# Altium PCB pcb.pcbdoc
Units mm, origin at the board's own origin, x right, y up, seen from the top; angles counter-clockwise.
Board outline 152.4 x 101.6 mm, 2 copper layers (Top Layer, Bottom Layer); 31 components, 27 nets, 116 pads, 42 vias.
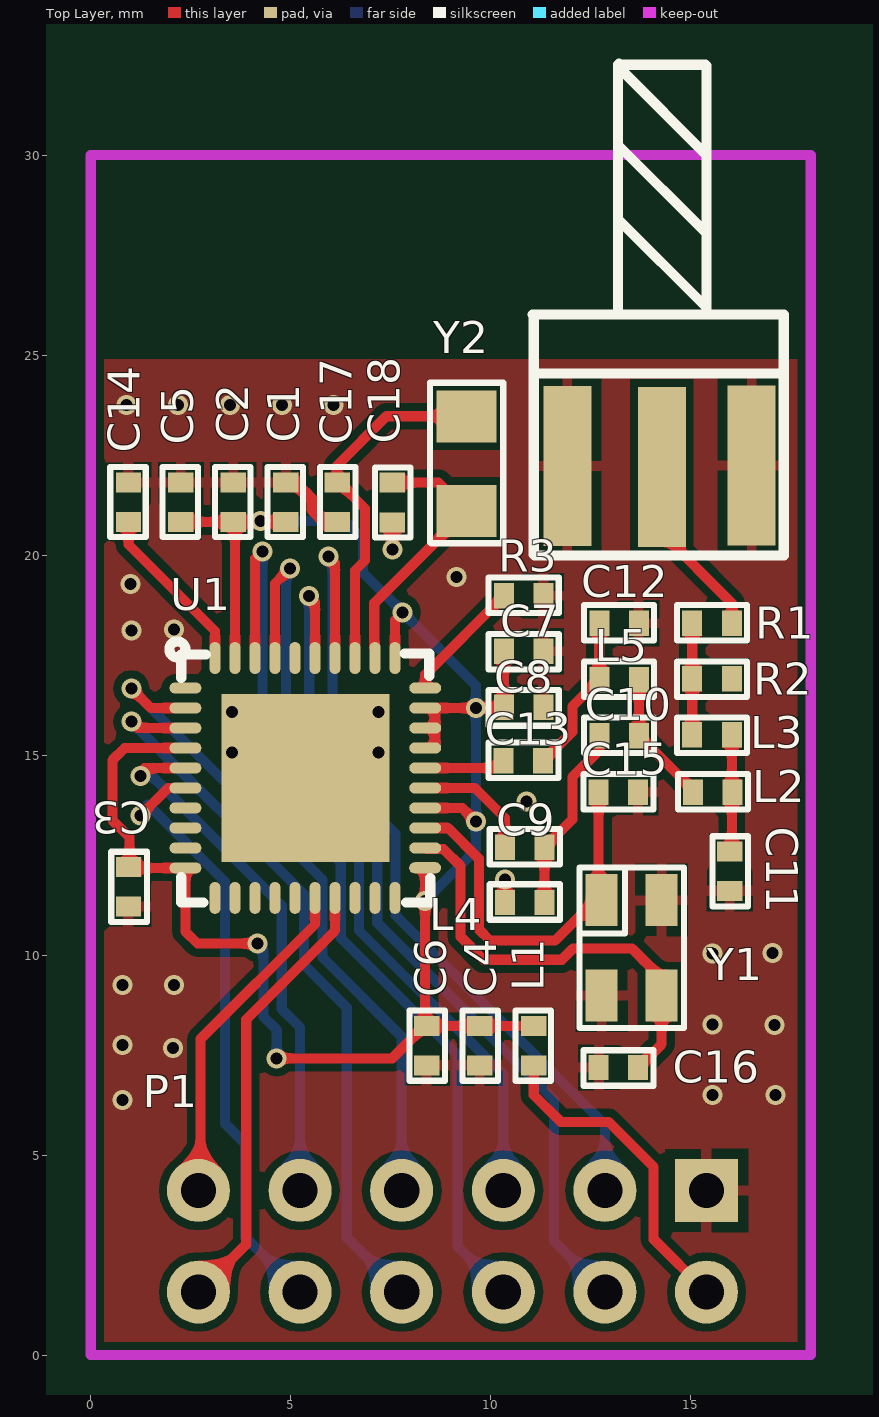
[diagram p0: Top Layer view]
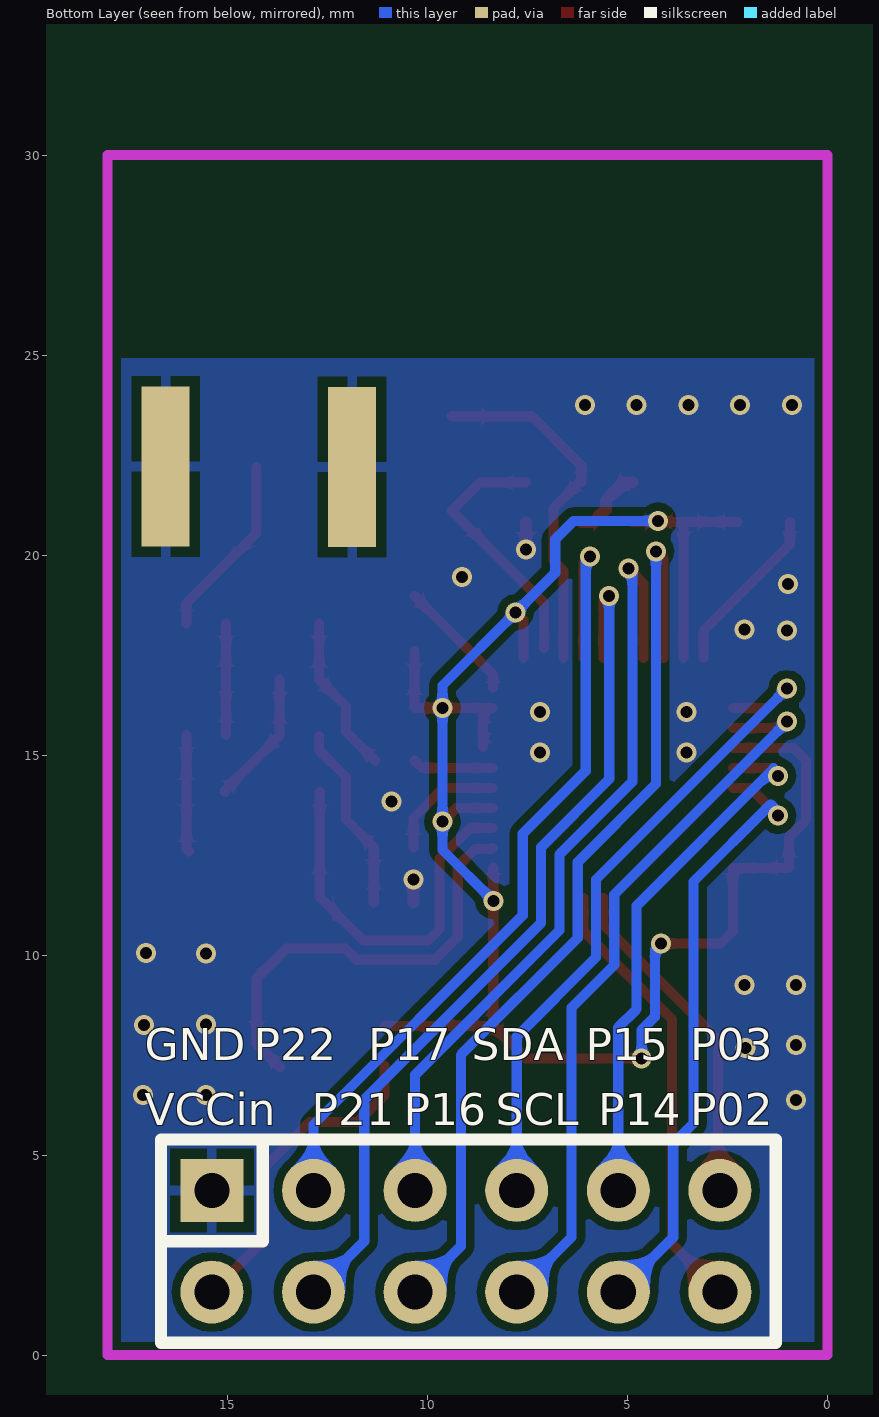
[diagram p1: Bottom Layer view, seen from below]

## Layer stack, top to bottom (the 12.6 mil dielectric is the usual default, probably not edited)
Top Solder: solder mask 0.0102, Solder Resist, Dk 3.5
Top Layer: signal copper 0.0356
Dielectric1: dielectric 0.32, FR-4, Dk 4.8
Bottom Layer: signal copper 0.0356
Bottom Solder: solder mask 0.0102, Solder Resist, Dk 3.5

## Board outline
-67.589,-36.627 84.811,-36.627 84.811,64.973 -67.589,64.973

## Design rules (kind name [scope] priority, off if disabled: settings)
Clearance [All] p1: gap=0.203 ignorepadtopadclearanceinfootprint=FALSE
MinimumSolderMaskSliver [All] p1 off: minsoldermaskwidth=0.254
PolygonConnect PolygonConnect_86 [All vs IsNamedPolygon('Top Layer-GND')] p1: thpad.connectstyle=Relief thpad.reliefconductorwidth=0.254 thpad.reliefentries=4 thpad.polygonreliefangle="90 Angle" thpad.airgapwidth=0.254 smdpad.connectstyle=Relief smdpad.reliefconductorwidth=0.254 smdpad.reliefentries=4 smdpad.polygonreliefangle="90 Angle" smdpad.airgapwidth=0.254 via.connectstyle=Direct via.reliefconductorwidth=0.254 via.reliefentries=4 via.polygonreliefangle="90 Angle" via.airgapwidth=0.254
PolygonConnect PolygonConnect_85 [All vs IsNamedPolygon('GND_L01_P020')] p2: thpad.connectstyle=Relief thpad.reliefconductorwidth=0.254 thpad.reliefentries=4 thpad.polygonreliefangle="90 Angle" thpad.airgapwidth=0.254 smdpad.connectstyle=Relief smdpad.reliefconductorwidth=0.254 smdpad.reliefentries=4 smdpad.polygonreliefangle="90 Angle" smdpad.airgapwidth=0.254 via.connectstyle=Direct via.reliefconductorwidth=0.254 via.reliefentries=4 via.polygonreliefangle="90 Angle" via.airgapwidth=0.254
PolygonConnect PolygonConnect_84 [All vs IsNamedPolygon('Bottom Layer-GND')] p3: thpad.connectstyle=Relief thpad.reliefconductorwidth=0.254 thpad.reliefentries=4 thpad.polygonreliefangle="90 Angle" thpad.airgapwidth=0.254 smdpad.connectstyle=Relief smdpad.reliefconductorwidth=0.254 smdpad.reliefentries=4 smdpad.polygonreliefangle="90 Angle" smdpad.airgapwidth=0.254 via.connectstyle=Direct via.reliefconductorwidth=0.254 via.reliefentries=4 via.polygonreliefangle="90 Angle" via.airgapwidth=0.254
PolygonConnect PolygonConnect_83 [All vs IsNamedPolygon('AGND-top')] p4: thpad.connectstyle=Relief thpad.reliefconductorwidth=0.508 thpad.reliefentries=4 thpad.polygonreliefangle="90 Angle" thpad.airgapwidth=0.254 smdpad.connectstyle=Relief smdpad.reliefconductorwidth=0.508 smdpad.reliefentries=4 smdpad.polygonreliefangle="90 Angle" smdpad.airgapwidth=0.254 via.connectstyle=Direct via.reliefconductorwidth=0.254 via.reliefentries=4 via.polygonreliefangle="90 Angle" via.airgapwidth=0.254
PolygonConnect PolygonConnect_82 [All vs IsNamedPolygon('Totalcurrent-bottom')] p5: thpad.connectstyle=Relief thpad.reliefconductorwidth=0.508 thpad.reliefentries=4 thpad.polygonreliefangle="90 Angle" thpad.airgapwidth=0.254 smdpad.connectstyle=Relief smdpad.reliefconductorwidth=0.508 smdpad.reliefentries=4 smdpad.polygonreliefangle="90 Angle" smdpad.airgapwidth=0.254 via.connectstyle=Direct via.reliefconductorwidth=0.254 via.reliefentries=4 via.polygonreliefangle="90 Angle" via.airgapwidth=0.254
PolygonConnect PolygonConnect_81 [All vs IsNamedPolygon('GND-top')] p6: thpad.connectstyle=Relief thpad.reliefconductorwidth=0.508 thpad.reliefentries=4 thpad.polygonreliefangle="90 Angle" thpad.airgapwidth=0.254 smdpad.connectstyle=Relief smdpad.reliefconductorwidth=0.508 smdpad.reliefentries=4 smdpad.polygonreliefangle="90 Angle" smdpad.airgapwidth=0.254 via.connectstyle=Direct via.reliefconductorwidth=0.254 via.reliefentries=4 via.polygonreliefangle="90 Angle" via.airgapwidth=0.254
PolygonConnect PolygonConnect_80 [All vs IsNamedPolygon('GND-bottom')] p7: thpad.connectstyle=Relief thpad.reliefconductorwidth=0.508 thpad.reliefentries=4 thpad.polygonreliefangle="90 Angle" thpad.airgapwidth=0.254 smdpad.connectstyle=Relief smdpad.reliefconductorwidth=0.508 smdpad.reliefentries=4 smdpad.polygonreliefangle="90 Angle" smdpad.airgapwidth=0.254 via.connectstyle=Direct via.reliefconductorwidth=0.254 via.reliefentries=4 via.polygonreliefangle="90 Angle" via.airgapwidth=0.254
PolygonConnect PolygonConnect_79 [All vs IsNamedPolygon('AGND-bottom')] p8: thpad.connectstyle=Relief thpad.reliefconductorwidth=0.508 thpad.reliefentries=4 thpad.polygonreliefangle="90 Angle" thpad.airgapwidth=0.254 smdpad.connectstyle=Relief smdpad.reliefconductorwidth=0.508 smdpad.reliefentries=4 smdpad.polygonreliefangle="90 Angle" smdpad.airgapwidth=0.254 via.connectstyle=Direct via.reliefconductorwidth=0.254 via.reliefentries=4 via.polygonreliefangle="90 Angle" via.airgapwidth=0.254
PolygonConnect PolygonConnect_78 [All vs IsNamedPolygon('AGND-BOTTOM')] p9: thpad.connectstyle=Relief thpad.reliefconductorwidth=0.508 thpad.reliefentries=4 thpad.polygonreliefangle="90 Angle" thpad.airgapwidth=0.254 smdpad.connectstyle=Relief smdpad.reliefconductorwidth=0.508 smdpad.reliefentries=4 smdpad.polygonreliefangle="90 Angle" smdpad.airgapwidth=0.254 via.connectstyle=Direct via.reliefconductorwidth=0.254 via.reliefentries=4 via.polygonreliefangle="90 Angle" via.airgapwidth=0.254
PolygonConnect PolygonConnect_77 [All vs IsNamedPolygon('AGND-BOTTOM')] p10: thpad.connectstyle=Relief thpad.reliefconductorwidth=0.508 thpad.reliefentries=4 thpad.polygonreliefangle="90 Angle" thpad.airgapwidth=0.254 smdpad.connectstyle=Relief smdpad.reliefconductorwidth=0.508 smdpad.reliefentries=4 smdpad.polygonreliefangle="90 Angle" smdpad.airgapwidth=0.254 via.connectstyle=Direct via.reliefconductorwidth=0.254 via.reliefentries=4 via.polygonreliefangle="90 Angle" via.airgapwidth=0.254
PolygonConnect PolygonConnect_76 [All vs IsNamedPolygon('Totalcurrent-top')] p11: thpad.connectstyle=Relief thpad.reliefconductorwidth=0.508 thpad.reliefentries=4 thpad.polygonreliefangle="90 Angle" thpad.airgapwidth=0.254 smdpad.connectstyle=Relief smdpad.reliefconductorwidth=0.508 smdpad.reliefentries=4 smdpad.polygonreliefangle="90 Angle" smdpad.airgapwidth=0.254 via.connectstyle=Direct via.reliefconductorwidth=0.254 via.reliefentries=4 via.polygonreliefangle="90 Angle" via.airgapwidth=0.254
PolygonConnect PolygonConnect_75 [All vs IsNamedPolygon('Totalcurrent-bottom')] p12: thpad.connectstyle=Relief thpad.reliefconductorwidth=0.508 thpad.reliefentries=4 thpad.polygonreliefangle="90 Angle" thpad.airgapwidth=0.254 smdpad.connectstyle=Relief smdpad.reliefconductorwidth=0.508 smdpad.reliefentries=4 smdpad.polygonreliefangle="90 Angle" smdpad.airgapwidth=0.254 via.connectstyle=Direct via.reliefconductorwidth=0.254 via.reliefentries=4 via.polygonreliefangle="90 Angle" via.airgapwidth=0.254
PolygonConnect PolygonConnect_74 [All vs IsNamedPolygon('Totalcurrent-bottom')] p13: thpad.connectstyle=Relief thpad.reliefconductorwidth=0.508 thpad.reliefentries=4 thpad.polygonreliefangle="90 Angle" thpad.airgapwidth=0.254 smdpad.connectstyle=Relief smdpad.reliefconductorwidth=0.508 smdpad.reliefentries=4 smdpad.polygonreliefangle="90 Angle" smdpad.airgapwidth=0.254 via.connectstyle=Direct via.reliefconductorwidth=0.254 via.reliefentries=4 via.polygonreliefangle="90 Angle" via.airgapwidth=0.254
PolygonConnect PolygonConnect_73 [All vs IsNamedPolygon('Totalcurrent-top')] p14: connectstyle=Relief reliefconductorwidth=0.254 reliefentries=4 polygonreliefangle="90 Angle" airgapwidth=0.254
PolygonConnect PolygonConnect_72 [All vs IsNamedPolygon('Totalcurrent-top')] p15: thpad.connectstyle=Relief thpad.reliefconductorwidth=0.508 thpad.reliefentries=4 thpad.polygonreliefangle="90 Angle" thpad.airgapwidth=0.254 smdpad.connectstyle=Relief smdpad.reliefconductorwidth=0.508 smdpad.reliefentries=4 smdpad.polygonreliefangle="90 Angle" smdpad.airgapwidth=0.254 via.connectstyle=Direct via.reliefconductorwidth=0.254 via.reliefentries=4 via.polygonreliefangle="90 Angle" via.airgapwidth=0.254
PolygonConnect PolygonConnect_71 [All vs IsNamedPolygon('Totalcurrent-top')] p16: connectstyle=Relief reliefconductorwidth=0.254 reliefentries=4 polygonreliefangle="45 Angle" airgapwidth=0.254
PolygonConnect PolygonConnect_70 [All vs IsNamedPolygon('GND-top')] p17: connectstyle=Relief reliefconductorwidth=0.254 reliefentries=4 polygonreliefangle="45 Angle" airgapwidth=0.254
PolygonConnect PolygonConnect_69 [All vs IsNamedPolygon('GND-bottom')] p18: connectstyle=Relief reliefconductorwidth=0.254 reliefentries=4 polygonreliefangle="45 Angle" airgapwidth=0.254
PolygonConnect PolygonConnect_68 [All vs IsNamedPolygon('GND-top')] p19: connectstyle=Relief reliefconductorwidth=0.254 reliefentries=4 polygonreliefangle="45 Angle" airgapwidth=0.254
PolygonConnect PolygonConnect_67 [All vs IsNamedPolygon('GND-top')] p20: connectstyle=Relief reliefconductorwidth=0.254 reliefentries=4 polygonreliefangle="45 Angle" airgapwidth=0.254
PolygonConnect PolygonConnect_66 [All vs IsNamedPolygon('Totalcurrent-bottom')] p21: connectstyle=Relief reliefconductorwidth=0.254 reliefentries=4 polygonreliefangle="45 Angle" airgapwidth=0.254
PolygonConnect PolygonConnect_65 [All vs IsNamedPolygon('AGND-BOTTOM')] p22: connectstyle=Relief reliefconductorwidth=0.254 reliefentries=4 polygonreliefangle="45 Angle" airgapwidth=0.254
PolygonConnect PolygonConnect_64 [All vs IsNamedPolygon('Totalcurrent-bottom')] p23: connectstyle=Relief reliefconductorwidth=0.254 reliefentries=4 polygonreliefangle="45 Angle" airgapwidth=0.254
PolygonConnect PolygonConnect_63 [All vs IsNamedPolygon('AGND-BOTTOM')] p24: connectstyle=Relief reliefconductorwidth=0.254 reliefentries=4 polygonreliefangle="45 Angle" airgapwidth=0.254
PolygonConnect PolygonConnect_62 [All vs IsNamedPolygon('AGND-BOTTOM')] p25: connectstyle=Relief reliefconductorwidth=0.254 reliefentries=4 polygonreliefangle="45 Angle" airgapwidth=0.254
PolygonConnect PolygonConnect_61 [All vs IsNamedPolygon('Totalcurrent-bottom')] p26: connectstyle=Relief reliefconductorwidth=0.254 reliefentries=4 polygonreliefangle="45 Angle" airgapwidth=0.254
PolygonConnect PolygonConnect_60 [All vs IsNamedPolygon('AGND2-top')] p27: connectstyle=Relief reliefconductorwidth=0.254 reliefentries=4 polygonreliefangle="45 Angle" airgapwidth=0.254
PolygonConnect PolygonConnect_59 [All vs IsNamedPolygon('AGND-BOTTOM')] p28: connectstyle=Relief reliefconductorwidth=0.254 reliefentries=4 polygonreliefangle="45 Angle" airgapwidth=0.254
PolygonConnect PolygonConnect_58 [All vs IsNamedPolygon('TotalcurrentLayer-bottom')] p29: connectstyle=Relief reliefconductorwidth=0.254 reliefentries=4 polygonreliefangle="45 Angle" airgapwidth=0.254
PolygonConnect PolygonConnect_57 [All vs IsNamedPolygon('TotalcurrentLayer-top')] p30: connectstyle=Relief reliefconductorwidth=0.254 reliefentries=4 polygonreliefangle="45 Angle" airgapwidth=0.254
PolygonConnect PolygonConnect_56 [All vs IsNamedPolygon('TotalcurrentLayer-No Net')] p31: connectstyle=Relief reliefconductorwidth=0.254 reliefentries=4 polygonreliefangle="45 Angle" airgapwidth=0.254
PolygonConnect PolygonConnect_55 [All vs IsNamedPolygon('TotalcurrentLayer-No Net')] p32: connectstyle=Relief reliefconductorwidth=0.254 reliefentries=4 polygonreliefangle="45 Angle" airgapwidth=0.254
PolygonConnect PolygonConnect_54 [All vs IsNamedPolygon('TotalcurrentLayer-No Net')] p33: connectstyle=Direct reliefconductorwidth=0.254 reliefentries=4 polygonreliefangle="90 Angle" airgapwidth=0.254
PolygonConnect PolygonConnect_53 [InNet('TOTALCURRENTOUT') vs IsNamedPolygon('TotalcurrentLayer-No Net')] p34: connectstyle=Relief reliefconductorwidth=0.254 reliefentries=4 polygonreliefangle="45 Angle" airgapwidth=0.254
PolygonConnect PolygonConnect_52 [All vs IsNamedPolygon('TotalcurrentLayer-No Net')] p35: connectstyle=Relief reliefconductorwidth=0.254 reliefentries=4 polygonreliefangle="45 Angle" airgapwidth=0.254
PolygonConnect PolygonConnect_51 [All vs IsNamedPolygon('Bottom-Layer-GND')] p36: connectstyle=Relief reliefconductorwidth=0.254 reliefentries=4 polygonreliefangle="45 Angle" airgapwidth=0.254
PolygonConnect PolygonConnect_50 [All vs IsNamedPolygon('Bottom-Layer-GND')] p37: connectstyle=Relief reliefconductorwidth=0.254 reliefentries=4 polygonreliefangle="45 Angle" airgapwidth=0.254
PolygonConnect PolygonConnect_49 [InNet('GND') vs IsNamedPolygon('Top Layer-No Net')] p38: connectstyle=Relief reliefconductorwidth=0.508 reliefentries=4 polygonreliefangle="90 Angle" airgapwidth=0.254
PolygonConnect PolygonConnect_48 [All vs IsNamedPolygon('bottom-agnd')] p39: connectstyle=Relief reliefconductorwidth=0.508 reliefentries=4 polygonreliefangle="90 Angle" airgapwidth=0.254
PolygonConnect PolygonConnect_47 [All vs IsNamedPolygon('bottom-gnd')] p40: connectstyle=Relief reliefconductorwidth=0.508 reliefentries=4 polygonreliefangle="90 Angle" airgapwidth=0.254
PolygonConnect PolygonConnect_46 [All vs IsNamedPolygon('bottom-gnd')] p41: connectstyle=Relief reliefconductorwidth=0.508 reliefentries=4 polygonreliefangle="90 Angle" airgapwidth=0.254
PolygonConnect PolygonConnect_45 [All vs IsNamedPolygon('top-agnd')] p42: connectstyle=Relief reliefconductorwidth=0.508 reliefentries=4 polygonreliefangle="90 Angle" airgapwidth=0.254
PolygonConnect PolygonConnect_44 [All vs IsNamedPolygon('top-gnd')] p43: connectstyle=Relief reliefconductorwidth=0.508 reliefentries=4 polygonreliefangle="90 Angle" airgapwidth=0.254
PolygonConnect PolygonConnect_43 [All vs IsNamedPolygon('Topagndlayer-No Net')] p44: connectstyle=Relief reliefconductorwidth=0.508 reliefentries=4 polygonreliefangle="90 Angle" airgapwidth=0.254
PolygonConnect PolygonConnect_42 [All vs IsNamedPolygon('Topgndlayer-No Net')] p45: connectstyle=Relief reliefconductorwidth=0.508 reliefentries=4 polygonreliefangle="90 Angle" airgapwidth=0.254
PolygonConnect PolygonConnect_41 [All vs IsNamedPolygon('bottomagnd')] p46: connectstyle=Relief reliefconductorwidth=0.508 reliefentries=4 polygonreliefangle="90 Angle" airgapwidth=0.254
PolygonConnect PolygonConnect_40 [All vs IsNamedPolygon('bottomgnd')] p47: connectstyle=Relief reliefconductorwidth=0.508 reliefentries=4 polygonreliefangle="90 Angle" airgapwidth=0.254
PolygonConnect PolygonConnect_39 [InNet('CURRENT') vs IsNamedPolygon('Topgndlayer-No Net')] p48: connectstyle=Relief reliefconductorwidth=0.508 reliefentries=4 polygonreliefangle="90 Angle" airgapwidth=0.254
PolygonConnect PolygonConnect_38 [All vs IsNamedPolygon('Topagndlayer-No Net')] p49: connectstyle=Direct reliefconductorwidth=0.254 reliefentries=4 polygonreliefangle="90 Angle" airgapwidth=0.254
PolygonConnect PolygonConnect_37 [All vs IsNamedPolygon('Topgndlayer-No Net')] p50: connectstyle=Relief reliefconductorwidth=0.508 reliefentries=4 polygonreliefangle="90 Angle" airgapwidth=0.254
PolygonConnect PolygonConnect_36 [All vs IsNamedPolygon('bottomagnd')] p51: connectstyle=Relief reliefconductorwidth=0.508 reliefentries=4 polygonreliefangle="90 Angle" airgapwidth=0.254
PolygonConnect PolygonConnect_35 [All vs IsNamedPolygon('Topgndlayer-No Net')] p52: connectstyle=Relief reliefconductorwidth=0.508 reliefentries=4 polygonreliefangle="90 Angle" airgapwidth=0.254
PolygonConnect PolygonConnect_34 [InNet('16.8V') vs IsNamedPolygon('bottomgnd')] p53: connectstyle=Relief reliefconductorwidth=0.508 reliefentries=4 polygonreliefangle="90 Angle" airgapwidth=0.254
PolygonConnect PolygonConnect_33 [All vs IsNamedPolygon('Topgndlayer-No Net')] p54: connectstyle=Relief reliefconductorwidth=508 reliefentries=4 polygonreliefangle="90 Angle" airgapwidth=0.254
PolygonConnect PolygonConnect_32 [All vs IsNamedPolygon('Topagndlayer-No Net')] p55: connectstyle=Relief reliefconductorwidth=0.7 reliefentries=4 polygonreliefangle="90 Angle" airgapwidth=0.254
PolygonConnect PolygonConnect_31 [All vs IsNamedPolygon('Topgndlayer-No Net')] p56: connectstyle=Relief reliefconductorwidth=0.508 reliefentries=4 polygonreliefangle="90 Angle" airgapwidth=0.254
PolygonConnect PolygonConnect_30 [All vs IsNamedPolygon('Topgndlayer-No Net')] p57: connectstyle=Relief reliefconductorwidth=0.254 reliefentries=4 polygonreliefangle="90 Angle" airgapwidth=0.254
PolygonConnect PolygonConnect_29 [All vs IsNamedPolygon('bottomgnd')] p58: connectstyle=Relief reliefconductorwidth=0.254 reliefentries=4 polygonreliefangle="90 Angle" airgapwidth=0.254
PolygonConnect PolygonConnect_28 [All vs IsNamedPolygon('bottomagnd')] p59: connectstyle=Relief reliefconductorwidth=0.254 reliefentries=4 polygonreliefangle="90 Angle" airgapwidth=0.254
PolygonConnect PolygonConnect_27 [All vs IsNamedPolygon('Topgndlayer-No Net')] p60: connectstyle=Relief reliefconductorwidth=0.254 reliefentries=4 polygonreliefangle="90 Angle" airgapwidth=0.254
PolygonConnect PolygonConnect_26 [InNet('AGND') vs IsNamedPolygon('Topagndlayer-No Net')] p61: connectstyle=Relief reliefconductorwidth=0.508 reliefentries=4 polygonreliefangle="90 Angle" airgapwidth=0.254
PolygonConnect PolygonConnect_25 [All vs IsNamedPolygon('bottomagnd')] p62: connectstyle=Direct reliefconductorwidth=0.254 reliefentries=4 polygonreliefangle="90 Angle" airgapwidth=0.254
PolygonConnect PolygonConnect_24 [All vs IsNamedPolygon('bottomgnd')] p63: connectstyle=Direct reliefconductorwidth=0.254 reliefentries=4 polygonreliefangle="90 Angle" airgapwidth=0.254
PolygonConnect PolygonConnect_23 [All vs IsNamedPolygon('bottomagnd')] p64: connectstyle=Direct reliefconductorwidth=0.254 reliefentries=4 polygonreliefangle="90 Angle" airgapwidth=0.254
PolygonConnect PolygonConnect_22 [All vs IsNamedPolygon('bottomagnd')] p65: connectstyle=Direct reliefconductorwidth=0.254 reliefentries=4 polygonreliefangle="90 Angle" airgapwidth=0.254
PolygonConnect PolygonConnect_21 [All vs IsNamedPolygon('Topgndlayer-No Net')] p66: connectstyle=Direct reliefconductorwidth=0.254 reliefentries=4 polygonreliefangle="90 Angle" airgapwidth=0.254
PolygonConnect PolygonConnect_20 [All vs IsNamedPolygon('Topagndlayer-No Net')] p67: connectstyle=Direct reliefconductorwidth=0.254 reliefentries=4 polygonreliefangle="90 Angle" airgapwidth=0.254
PolygonConnect PolygonConnect_19 [All vs IsNamedPolygon('Topagndlayer-No Net')] p68: connectstyle=Direct reliefconductorwidth=0.254 reliefentries=4 polygonreliefangle="90 Angle" airgapwidth=0.254
PolygonConnect PolygonConnect_18 [All vs IsNamedPolygon('Topagndlayer-No Net')] p69: connectstyle=Direct reliefconductorwidth=0.254 reliefentries=4 polygonreliefangle="90 Angle" airgapwidth=0.254
PolygonConnect PolygonConnect_17 [All vs IsNamedPolygon('Topgndlayer-No Net')] p70: connectstyle=Direct reliefconductorwidth=0.254 reliefentries=4 polygonreliefangle="90 Angle" airgapwidth=0.254
PolygonConnect PolygonConnect_16 [InNet('AGND') vs IsNamedPolygon('toplayer-No Net')] p71: connectstyle=Direct reliefconductorwidth=0.254 reliefentries=4 polygonreliefangle="90 Angle" airgapwidth=0.254
PolygonConnect PolygonConnect_15 [All vs IsNamedPolygon('toplayer-No Net')] p72: connectstyle=Direct reliefconductorwidth=0.254 reliefentries=4 polygonreliefangle="90 Angle" airgapwidth=0.254
PolygonConnect PolygonConnect_14 [InNet('AGND') vs IsNamedPolygon('bottomlayer-No Net')] p73: connectstyle=Direct reliefconductorwidth=0.254 reliefentries=4 polygonreliefangle="90 Angle" airgapwidth=0.254
PolygonConnect PolygonConnect_13 [InNet('AGND') vs IsNamedPolygon('toplayer-No Net')] p74: connectstyle=Direct reliefconductorwidth=0.254 reliefentries=4 polygonreliefangle="90 Angle" airgapwidth=0.254
PolygonConnect PolygonConnect_12 [InNet('AGND') vs IsNamedPolygon('toplayer-No Net')] p75: connectstyle=Direct reliefconductorwidth=0.254 reliefentries=4 polygonreliefangle="90 Angle" airgapwidth=0.254
PolygonConnect PolygonConnect_11 [All vs IsNamedPolygon('toplayer-No Net')] p76: connectstyle=Direct reliefconductorwidth=0.254 reliefentries=4 polygonreliefangle="90 Angle" airgapwidth=0.254
PolygonConnect PolygonConnect_10 [All vs IsNamedPolygon('bottomlayer-No Net')] p77: connectstyle=Direct reliefconductorwidth=0.254 reliefentries=4 polygonreliefangle="90 Angle" airgapwidth=0.254
PolygonConnect PolygonConnect_9 [InNet('AGND') vs IsNamedPolygon('bottomlayer-No Net')] p78: connectstyle=Direct reliefconductorwidth=0.254 reliefentries=4 polygonreliefangle="90 Angle" airgapwidth=0.254
PolygonConnect PolygonConnect_8 [InNet('AGND') vs IsNamedPolygon('toplayer-No Net')] p79: connectstyle=Direct reliefconductorwidth=0.254 reliefentries=4 polygonreliefangle="90 Angle" airgapwidth=0.254
PolygonConnect PolygonConnect_7 [All vs IsNamedPolygon('bottomlayer-No Net')] p80: connectstyle=Direct reliefconductorwidth=0.254 reliefentries=4 polygonreliefangle="90 Angle" airgapwidth=0.254
PolygonConnect PolygonConnect_6 [All vs IsNamedPolygon('toplayer-No Net')] p81: connectstyle=Direct reliefconductorwidth=0.254 reliefentries=4 polygonreliefangle="90 Angle" airgapwidth=0.254
PolygonConnect PolygonConnect_5 [InNet('AGND') vs IsNamedPolygon('toplayer-No Net')] p82: connectstyle=Direct reliefconductorwidth=0.254 reliefentries=4 polygonreliefangle="90 Angle" airgapwidth=0.254
PolygonConnect PolygonConnect_4 [InNet('AGND') vs IsNamedPolygon('Bottomlayer-No Net')] p83: connectstyle=Direct reliefconductorwidth=0.254 reliefentries=4 polygonreliefangle="90 Angle" airgapwidth=0.254
PolygonConnect PolygonConnect_3 [InNet('AGND') vs IsNamedPolygon('AGND_L01_P012')] p84: connectstyle=Direct reliefconductorwidth=0.254 reliefentries=4 polygonreliefangle="90 Angle" airgapwidth=0.254
PolygonConnect PolygonConnect_2 [InNet('AGND') vs IsNamedPolygon('AGND_L02_P010')] p85: connectstyle=Direct reliefconductorwidth=0.254 reliefentries=4 polygonreliefangle="90 Angle" airgapwidth=0.254
PolygonConnect PolygonConnect_1 [All vs IsNamedPolygon('Top Layer-No Net')] p86: connectstyle=Direct reliefconductorwidth=0.254 reliefentries=4 polygonreliefangle="90 Angle" airgapwidth=0.254
PolygonConnect [All] p87: connectstyle=Relief reliefconductorwidth=0.254 reliefentries=4 polygonreliefangle="90 Angle" airgapwidth=0.254
RoutingVias [All] p1: holewidth=0.711 width=1.27 viastyle="Through Hole" minholewidth=0.711 minwidth=1.27 maxholewidth=0.711 maxwidth=1.27
SilkToSilkClearance [All] p1 off: silktosilkclearance=0.254
SilkToSolderMaskClearance [IsPad] p1 off: minsilkscreentomaskgap=0.254 clearancetoexposedcopper=TRUE
SolderMaskExpansion [All] p1: expansion=0.102
Width [All] p1: maxlimit=2.54 minlimit=0.254 preferedwidth=0.6
27 further rules are at their usual default settings.

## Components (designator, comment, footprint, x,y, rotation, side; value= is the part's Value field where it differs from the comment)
C1 "100nF" 0402_SMALL 5.174,21.048 r90 top
C2 "100nF" 0402_SMALL 3.864,21.048 r90 top
C3 "100nF" 0402_SMALL 0.643,11.981 r270 top
C4 "2.2uF" 0402_SMALL 9.425,8.01 r270 top
C5 "1uF" 0402_SMALL 2.554,21.048 r90 top
C6 "100nF" 0402_SMALL 8.103,8.01 r270 top
C7 "100nF" 0402_SMALL 11.1,17.897 r180 top
C8 "220p" 0402_SMALL 11.1,16.49 r180 top
C9 "18p" 0402_SMALL 10.574,12.391 r0 top
C10 "1p" 0402_SMALL 12.932,15.178 r0 top
C11 "CAP" 0402_SMALL 15.672,12.37 r270 top
C12 "1p" 0402_SMALL 12.932,17.991 r0 top
C13 "18p" 0402_SMALL 10.541,14.554 r0 top
C14 "1uF" 0402_SMALL 1.245,21.048 r90 top
C15 "27p" 0402_SMALL 12.915,13.771 r0 top
C16 "27p" 0402_SMALL 13.466,7.489 r180 top
C17 "15p" 0402_SMALL 5.857,21.599 r270 top
C18 "15p" 0402_SMALL 7.239,21.59 r270 top
L1 "2nH" 0402_SMALL 11.375,7.459 r90 top
L2 "1nH" 0402_SMALL 15.278,13.771 r0 top
L3 "1nH" 0402_SMALL 15.808,15.805 r180 top
L4 "INDUCTOR" 0402_SMALL 10.574,11.012 r0 top
L5 "2nH" 0402_SMALL 12.932,16.584 r0 top
P1 "Header 12" M-IDC12M 15.4,4.12 r180 top
R1 "0R" 0402_SMALL 15.257,17.991 r0 top
R2 "0R" 0402_SMALL 15.808,17.211 r180 top
R3 "56K" 0402_SMALL 10.549,18.677 r0 top
U1 "CC2540" CC2530_QFN 2.274,16.685 r0 top
Y1 "32M" CY_3225 13.843,11.278 r270 top
Y2 "32.768K" CRYSTAL_3215 8.712,22.606 r270 top
? "ANT_SMA" SMA_EB 14.242,22.314 r90 top

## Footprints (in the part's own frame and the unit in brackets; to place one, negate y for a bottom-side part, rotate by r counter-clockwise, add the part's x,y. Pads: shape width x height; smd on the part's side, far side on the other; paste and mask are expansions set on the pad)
0402_SMALL [mm]
  rect 0.5x0.635 smd: 1(-0.22,0.301) 2(0.771,0.301)
  silkscreen extent -0.6,-0.13 1.15,0.76
CC2530_QFN [mm]
  oval 0.8x0.28 smd: 1(0.09,-0.009) 2(0.09,-0.509) 3(0.09,-1.009) 4(0.09,-1.509) 5(0.09,-2.009) 6(0.09,-2.509) 7(0.09,-3.009) 8(0.09,-3.509) 9(0.09,-4.009) 10(0.09,-4.509) 21(6.085,-4.505) 22(6.087,-4.009) 23(6.087,-3.509) 24(6.087,-3.009) 25(6.087,-2.509) 26(6.087,-2.009) 27(6.087,-1.509) 28(6.087,-1.009) 29(6.087,-0.509) 30(6.087,-0.009)
  oval 0.28x0.8 smd: 11(0.832,-5.258) 12(1.332,-5.258) 13(1.832,-5.258) 14(2.332,-5.258) 15(2.832,-5.258) 16(3.332,-5.258) 17(3.832,-5.258) 18(4.332,-5.258) 19(4.832,-5.258) 20(5.332,-5.258) 31(5.332,0.739) 32(4.832,0.739) 33(4.332,0.739) 34(3.832,0.739) 35(3.332,0.739) 36(2.832,0.739) 37(2.332,0.739) 38(1.832,0.739) 39(1.332,0.739) 40(0.832,0.739)
  rect 4.2x4.2 smd: 41(3.089,-2.259)
  silkscreen extent -0.31,-5.37 6.21,1.16
CRYSTAL_3215 [mm]
  rect 1.3x1.5 smd: 1(-0.862,0.685) 2(1.5,0.685)
  silkscreen extent -1.7,-0.23 2.31,1.6
CY_3225 [mm]
  rect 1.3x0.8 smd: 1(-0.095,-1.07) 2(2.293,-1.07) 3(2.293,0.428) 4(-0.095,0.428)
  silkscreen extent -0.91,-1.63 3.11,0.99
M-IDC12M [mil]
  rect 62x62 hole 34.65: 1(0.31,0.22)
  round 62 hole 34.65: 2(0.31,100.22) 3(100.31,0.22) 4(100.31,100.22) 5(200.31,0.22) 6(200.31,100.22) 7(300.31,0.22) 8(300.31,100.22) 9(400.31,0.22) 10(400.31,100.22) 11(500.31,0.22) 12(500.31,100.22)
SMA_EB [mm]
  rect 4x1.2 smd: 1(-0.114,-0.033) 2(-0.089,2.329) 2(-0.076,-2.281)
  rect 4x1.2 smd far side: 2(-0.114,2.354) 2(-0.101,-2.306)
  silkscreen extent -2.32,-3.08 9.97,3.19

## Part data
C1 C2 C3 C4 C5 C6 C7 C8 C9 C10 C12 C13 C14 C15 C16 C17 C18: library part CAP, "Capacitor"
C11: "Capacitor"
L1 L2 L3 L5: library part INDUCTOR
P1: "Header, 12-Pin"
R1 R2 R3: library part RES2
Y1: library part CY_3225
Y2: library part CRYSTAL, "Crystal"

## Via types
v1: diameter 0.5, hole 0.3, Top Layer to Bottom Layer, 42 vias

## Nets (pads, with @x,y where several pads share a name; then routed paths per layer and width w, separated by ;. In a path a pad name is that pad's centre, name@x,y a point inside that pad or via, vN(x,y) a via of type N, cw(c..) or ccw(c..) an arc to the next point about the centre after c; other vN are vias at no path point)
GND: ?.2 C1.2 C2.2 C3.2 C4.2 C5.2 C6.2 C7.1 C8.1 C11.2 C12.2 C14.2 C15.2 C16.2 C17.2 C18.2 L4.1 P1.1 R3.2 U1.41 Y1.2 Y1.4 | length 3.1
  Top Layer w0.3: C1.2 5.091,21.819 5.544,21.366 5.544,21.133 5.849,20.828 C17.2 ; v1(7.54,20.138) C18.2 ; L4.1 v1(10.354,11.887)
  other v1: 0.787,6.375 15.545,6.502 17.12,6.502 2.057,7.671 0.787,7.747 17.094,8.255 15.545,8.268 0.787,9.246 2.083,9.246 15.545,10.033 17.043,10.049 10.897,13.843 3.531,15.062 7.188,15.062 3.531,16.078 7.188,16.078 1.016,18.11 2.083,18.141 0.991,19.279 9.144,19.456 0.889,23.749 2.184,23.749 3.48,23.749 4.775,23.749 6.071,23.749
Net_1: ?.1 R1.2 | length 4.6
  Top Layer w0.254: ?.1 14.275,20.549 16.027,18.796 R1.2
NetC9_1: C9.1 U1.25 | length 3
  Top Layer w0.254: U1.25 9.606,14.176 10.354,13.428 C9.1
NetC9_2: C9.2 C10.1 L4.2 | length 4.7
  Top Layer w0.254: L4.2 C9.2 12.04,13.387 12.04,14.45 12.713,15.123 C10.1
NetC10_2: C10.2 L2.1 L5.2 | length 3.4
  Top Layer w0.254: L5.2 C10.2 15.058,14.124 L2.1
NetC11_1: C11.1 L2.2 L3.1 | length 2.9
  Top Layer w0.254: C11.1 16.027,12.644 L3.1
NetC12_1: C12.1 C13.2 L5.1 | length 4
  Top Layer w0.254: C13.2 12.04,15.583 12.04,16.212 L5.1 C12.1
NetC13_1: C13.1 U1.26 | length 2
  Top Layer w0.254: U1.26 10.142,14.676 C13.1
NetC14_1: C14.1 U1.40 | length 4.3
  Top Layer w0.254: C14.1 0.944,20.265 3.107,18.102 U1.40
NetC15_1: C15.1 U1.23 Y1.1 | length 9.6
  Top Layer w0.254: U1.23 8.934,13.176 9.703,12.408 9.703,12.218 9.703,10.643 9.982,10.363 11.609,10.363 12.696,11.449 C15.1
NetC16_1: C16.1 U1.22 Y1.3 | length 11
  Top Layer w0.254: U1.22 8.387,12.65 8.814,12.65 9.246,12.218 9.246,10.453 9.818,9.881 11.773,9.881 12.053,10.16 13.534,10.16 14.271,9.423 Y1.3 14.271,7.773 C16.1
NetC17_1: C17.1 U1.33 Y2.1 | length 9
  Top Layer w0.254: U1.33 6.607,19.612 6.857,19.862 6.857,21.163 6.202,21.819 C17.1 6.158,22.236 7.39,23.468 Y2.1
NetC18_1: C18.1 U1.32 Y2.2 | length 6.5
  Top Layer w0.254: U1.32@7.087,17.678 7.087,18.796 Y2.2 8.694,21.81 C18.1
NetL3_2: L3.2 R1.1 R2.2 | length 2.8
  Top Layer w0.254: L3.2 R2.2 R1.1
NetR3_1: R3.1 U1.30 | length 3.1
  Top Layer w0.254: U1.30 8.362,17.011 R3.1
P02: P1.12 U1.17 | length 11.3
  Top Layer w0.254: P1.12 3.886,2.769 3.886,8.39 6.107,10.61 U1.17
P03: P1.11 U1.16 | length 8.5
  Top Layer w0.254: P1.11 2.739,4.162 2.739,7.895 5.607,10.763 U1.16
P14: P1.10 U1.6 | length 15.5
  Top Layer w0.254: v1(1.245,13.487) 1.933,14.176 U1.6
  Bottom Layer w0.254: v1(1.245,13.487) 1.245,13.589 1.422,13.767 3.353,11.836 3.353,5.791 3.861,5.283 3.861,2.946 P1.10
P15: P1.9 U1.5 | length 13.2
  Top Layer w0.254: v1@1.351,14.676 U1.5
  Bottom Layer w0.254: v1@1.351,14.676 1.351,14.658 4.775,11.235 4.775,8.648 5.232,8.19 P1.9
  other v1: 1.245,14.478
P16: P1.6 U1.38 | length 23.8
  Top Layer w0.254: U1.38 4.107,19.906 v1(4.293,20.091)
  Bottom Layer w0.254: v1(4.293,20.091) 4.293,14.275 6.248,12.319 6.248,10.426 9.169,7.505 9.169,2.718 P1.6
P17: P1.5 U1.37 | length 20.2
  Top Layer w0.254: U1.37 4.607,19.288 v1(4.978,19.66)
  Bottom Layer w0.254: v1(4.978,19.66) 4.881,19.562 4.881,14.333 6.706,12.508 6.706,10.615 10.312,7.008 P1.5
P21: P1.4 U1.35 | length 22.1
  Top Layer w0.254: v1(5.461,18.974) 5.607,18.828 U1.35
  Bottom Layer w0.254: v1(5.461,18.974) 5.461,14.4 7.163,12.698 7.163,10.804 11.582,6.385 11.582,2.845 P1.4
P22: P1.3 U1.34 | length 21.3
  Top Layer w0.254: v1(5.944,19.964) 6.107,19.801 U1.34
  Bottom Layer w0.254: v1(5.944,19.964) 6.045,19.863 6.045,14.605 7.62,13.03 7.62,10.994 12.852,5.761 P1.3
USB_M/SDA: P1.8 U1.3 | length 18.5
  Top Layer w0.254: v1(1.016,15.833) 1.173,15.676 U1.3
  Bottom Layer w0.254: v1(1.016,15.833) 5.334,11.515 5.334,9.752 6.401,8.685 6.401,2.946 P1.8
USB_P/SCL: P1.7 U1.2 | length 16.9
  Top Layer w0.254: v1(1.016,16.662) 1.502,16.176 U1.2
  Bottom Layer w0.254: v1(1.016,16.662) 5.791,11.887 5.791,9.941 7.772,7.96 P1.7
VCC: C1.1 C2.1 C3.1 C4.1 C5.1 C6.1 C7.2 C8.2 L1.2 U1.4 U1.10 U1.21 U1.24 U1.27 U1.28 U1.29 U1.31 U1.39 | length 50.1
  Top Layer w0.254: C5.1 C2.1 ; U1.4 0.85,15.176 0.54,14.865 0.54,13.372 0.969,12.943 0.969,12.176 U1.10 2.365,10.589 2.667,10.287 v1(4.166,10.287) ; U1.39 3.607,20.785 C2.1 ; v1(4.648,7.417) 7.54,7.417 8.327,8.204 8.353,8.179 C6.1 ; C1.1 C2.1 ; U1.31 7.607,18.376 v1(7.798,18.567) ; U1.21 8.359,8.274 C6.1 ; U1.24 9.286,13.676 v1(9.627,13.335) ; U1.29 U1.29@8.612,16.176 ; U1.27@8.612,15.202 U1.29@8.612,16.176 ; C7.2 C8.2 10.315,16.176 U1.29@8.612,16.176 ; L1.2 C4.1 C6.1
  Bottom Layer w0.254: v1(4.166,10.287) 4.318,10.135 4.318,8.458 4.648,8.128 v1(4.648,7.417) ; v1(4.242,20.853) 6.35,20.853 6.807,20.396 6.807,19.558 v1(7.798,18.567) 9.627,16.739 v1(9.627,16.18) v1(9.627,13.335) 9.627,12.624 v1(8.357,11.354)
VCCin: L1.1 P1.2 | length 8.2
  Top Layer w0.254: L1.1 11.074,6.502 11.747,5.829 12.941,5.829 14.072,4.699 14.072,2.896 P1.2
pads on no net: R2.1 U1.1 U1.7 U1.8 U1.9 U1.11 U1.12 U1.13 U1.14 U1.15 U1.18 U1.19 U1.20 U1.36

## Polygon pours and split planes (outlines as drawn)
GND on Top Layer "Top Layer-GND" (solid, remove dead copper, pour order 20): 0,30 0,0 18,0 18,30
GND on Bottom Layer "Bottom Layer-GND" (solid, remove dead copper, pour order 22): 0,0 0.127,0.127 18,0.127 18,30 0.051,30

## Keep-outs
Keep-Out Layer:
  lines w0.254: 0,0 18,0 18,30 0,30 0,0

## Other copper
Top Layer:
  pour cut-out: -0.127,24.917 -0.102,24.892 18,24.892 18,30 0,30
Bottom Layer:
  pour cut-out: 0,30 0,24.917 17.975,24.917 18,24.892 18,30

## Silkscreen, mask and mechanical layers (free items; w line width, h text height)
Bottom Overlay:
  text "P03" at 3.429,7.366 h0.8
  text "P15" at 6.044,7.366 h0.8
  text "SDA" at 8.9,7.366 h0.8
  text "P17" at 11.49,7.366 h0.8
  text "P22" at 14.346,7.366 h0.8
  text "GND" at 17.069,7.366 h0.8
  text "P02" at 3.429,5.74 h0.8
  text "P14" at 5.73,5.74 h0.8
  text "SCL" at 8.298,5.74 h0.8
  text "P16" at 10.6,5.74 h0.8
  text "P21" at 12.901,5.74 h0.8
  text "VCCin" at 17.069,5.74 h0.8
